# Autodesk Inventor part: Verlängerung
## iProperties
Created: 2008-01
Part Number: Verlängerung
Document SubType Name: Modeling
Designer: admin
Author: admin
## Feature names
1. Extrusion1
2. Bohrung1 [Hole]
3. Bohrung2 [Hole]
